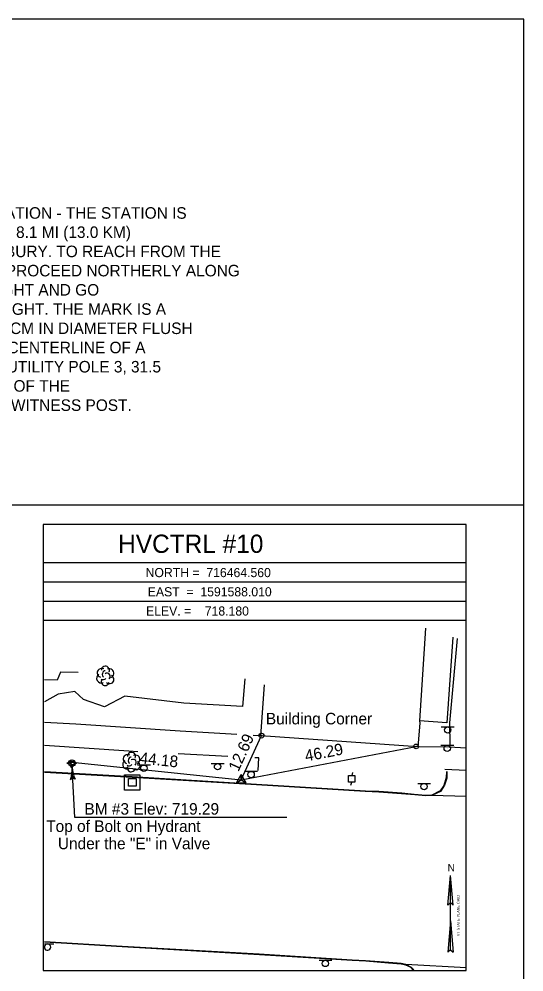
# Model space of a CAD drawing. Extents: x 1586965 to 1590952, y 716317 to 720029.
# Drawn here: x 1590820.9 to 1590952.2, y 716489.5 to 716737.4 of the extents above; entities that cross this region are included whole.
import ezdxf

# ---------------------------------------------------------------- set-up
doc = ezdxf.new("R2010")
doc.units = 0
for name, color, linetype in [('C_C', 7, 'Continuous'), ('CBP', 7, 'Continuous'), ('CPBM', 7, 'Continuous'), ('CPSM', 7, 'Continuous'), ('Default', 7, 'Continuous'), ('DS', 7, 'Continuous'), ('LAPB', 7, 'Continuous'), ('LBC', 7, 'Continuous'), ('LBF', 7, 'Continuous'), ('LTD', 7, 'Continuous'), ('NBL1', 7, 'Continuous'), ('NBL2', 7, 'Continuous'), ('NNA_P', 7, 'Continuous'), ('PET', 7, 'Continuous'), ('RC', 7, 'Continuous'), ('RDP', 7, 'Continuous'), ('RSW', 7, 'Continuous'), ('SSGN', 7, 'Continuous'), ('ULP', 7, 'Continuous'), ('UWFH', 7, 'Continuous')]:
    doc.layers.add(name, color=color, linetype=linetype)

msp = doc.modelspace()

# ---------------------------------------------------------------- linework, layer by layer
at = {"layer": 'CBP'}
for centre, radius in [((1590883.95, 716550.95), 0.625), ((1590883.95, 716550.95), 0.0833), ((1590924.14, 716548.14), 0.625), ((1590924.14, 716548.14), 0.0833), ((1590834.74, 716544), 0.625), ((1590834.74, 716544), 0.0833)]:
    msp.add_circle(centre, radius, dxfattribs=at)
at = {"layer": 'CPBM'}
for p, q in [((1590834.43, 716543.2), (1590834.43, 716544.2)), ((1590834.43, 716544.2), (1590835.43, 716544.2)), ((1590835.43, 716543.2), (1590834.43, 716543.2)), ((1590834.93, 716543.7), (1590834.93, 716543.7)), ((1590834.93, 716543.7), (1590834.93, 716543.7)), ((1590835.43, 716544.2), (1590835.43, 716543.2))]:
    msp.add_line(p, q, dxfattribs=at)
at = {"layer": 'CPSM'}
for p, q in [((1590877.42, 716538.69), (1590878.67, 716540.86)), ((1590879.92, 716538.69), (1590878.67, 716540.86)), ((1590878.67, 716539.42), (1590878.67, 716540.86)), ((1590877.42, 716538.69), (1590878.67, 716539.42)), ((1590877.42, 716538.69), (1590879.92, 716538.69)), ((1590878.67, 716539.42), (1590878.67, 716539.42)), ((1590878.67, 716539.42), (1590879.92, 716538.69))]:
    msp.add_line(p, q, dxfattribs=at)
at = {"layer": 'Default'}
for p, q in [((1590878.67, 716539.42), (1590883.95, 716550.95)), ((1590878.67, 716539.42), (1590924.14, 716548.14)), ((1590834.74, 716544), (1590878.67, 716539.42)), ((1590834.54, 716539.88), (1590834.72, 716540.37)), ((1590835.42, 716529.68), (1590834.71, 716542.7)), ((1590835.19, 716539.92), (1590834.96, 716540.39)), ((1590834.3, 716539.57), (1590834.87, 716539.85)), ((1590835.46, 716539.64), (1590834.87, 716539.85)), ((1590890.57, 716529.68), (1590835.42, 716529.68))]:
    msp.add_line(p, q, dxfattribs=at)
for centre, start, end in [((1590826.16, 716542.23), 341.9202, 3.1073), ((1590843.27, 716543.16), 183.1148, 204.3019)]:
    msp.add_arc(centre, 8.57, start, end, dxfattribs=at)
at = {"layer": 'DS'}
for p, q in [((1590848.34, 716540.77), (1590852.34, 716540.77)), ((1590848.34, 716536.77), (1590848.34, 716540.77)), ((1590852.34, 716540.77), (1590852.34, 716536.77)), ((1590849.34, 716537.77), (1590849.34, 716539.77)), ((1590849.34, 716539.77), (1590851.34, 716539.77)), ((1590851.34, 716537.77), (1590849.34, 716537.77)), ((1590850.35, 716538.77), (1590850.35, 716538.77)), ((1590850.35, 716538.77), (1590850.35, 716538.77)), ((1590851.34, 716539.77), (1590851.34, 716537.77)), ((1590852.34, 716536.77), (1590848.34, 716536.77))]:
    msp.add_line(p, q, dxfattribs=at)
at = {"layer": 'LAPB'}
msp.add_lwpolyline([(1590879.6, 716565.72), (1590879.04, 716558.49), (1590863.72, 716559.41), (1590848.43, 716561.17), (1590843.12, 716558.45), (1590837.66, 716560.37), (1590835.41, 716562.4), (1590831.03, 716561.73), (1590827.48, 716559.78)], dxfattribs=at)
at = {"layer": 'LBC'}
for points in [[(1590926.63, 716578.87), (1590925.04, 716554.77), (1590925.13, 716554.17), (1590924.63, 716547.99), (1590883.81, 716550.89), (1590884.72, 716564.13)], [(1590836.24, 716567.34), (1590831.64, 716567.44), (1590830.83, 716565.35), (1590827.48, 716565.47)]]:
    msp.add_lwpolyline(points, dxfattribs=at)
at = {"layer": 'LBF'}
msp.add_lwpolyline([(1590933.71, 716576.58), (1590932.16, 716554.31), (1590925.04, 716554.77)], dxfattribs=at)
at = {"layer": 'LTD'}
for p, q in [((1590843.29, 716566.54), (1590843.29, 716566.54)), ((1590843.29, 716566.54), (1590843.29, 716566.54)), ((1590850.07, 716544.12), (1590850.07, 716544.12)), ((1590850.07, 716544.12), (1590850.07, 716544.12))]:
    msp.add_line(p, q, dxfattribs=at)
for centre in [(1590843.34, 716567.97), (1590850.12, 716545.55)]:
    msp.add_arc(centre, 1.05, 335.5272, 180.9563, dxfattribs=at)
for centre, major_axis, ratio, start_param, end_param in [((1590842.5, 716567.2), (1.21, -0.51), 0.895232, 1.570796, 4.712389), ((1590843.08, 716566.99), (-0.208, -0.792), 0.645439, 3.141593, 6.283185), ((1590844.33, 716567.12), (-1.14, -0.48), 0.949671, 1.570796, 4.712389), ((1590842.21, 716565.83), (0.58, -1.04), 0.959034, 3.141593, 6.283185), ((1590843.29, 716565.04), (0.26, 1.06), 0.942809, 1.570796, 4.712389), ((1590842.83, 716565.78), (-0.625, -0.083), 0.423636, 0, 3.141593), ((1590843.79, 716566.37), (-0.5, 0.667), 0.989748, 3.141593, 6.283185), ((1590844.29, 716565.7), (-1.09, 0.79), 0.841452, 1.570796, 4.712389), ((1590849.28, 716544.79), (1.21, -0.51), 0.895232, 1.570796, 4.712389), ((1590849.86, 716544.58), (-0.208, -0.792), 0.645439, 3.141593, 6.283185), ((1590851.11, 716544.7), (-1.14, -0.48), 0.949671, 1.570796, 4.712389), ((1590848.99, 716543.41), (0.58, -1.04), 0.959034, 3.141593, 6.283185), ((1590850.07, 716542.62), (0.26, 1.06), 0.942809, 1.570796, 4.712389), ((1590849.61, 716543.37), (-0.625, -0.083), 0.423636, 0, 3.141593), ((1590850.57, 716543.95), (-0.5, 0.667), 0.989748, 3.141593, 6.283185), ((1590851.07, 716543.29), (-1.09, 0.79), 0.841452, 1.570796, 4.712389)]:
    msp.add_ellipse(centre, major_axis=major_axis, ratio=ratio, start_param=start_param, end_param=end_param, dxfattribs=at)
at = {"layer": 'NBL1'}
msp.add_lwpolyline([(1590312.19, 716317.36), (1590952.19, 716317.36), (1590952.19, 716737.36), (1590312.19, 716737.36)], close=True, dxfattribs=at)
at = {"layer": 'NBL2'}
for p, q in [((1590312.19, 716611.03), (1590952.19, 716611.03)), ((1590937.19, 716595.86), (1590827.19, 716595.86)), ((1590937.19, 716590.86), (1590827.19, 716590.86)), ((1590937.19, 716585.86), (1590827.19, 716585.86)), ((1590937.19, 716580.86), (1590827.19, 716580.86))]:
    msp.add_line(p, q, dxfattribs=at)
msp.add_lwpolyline([(1590827.19, 716489.86), (1590937.19, 716489.86), (1590937.19, 716605.86), (1590827.19, 716605.86)], close=True, dxfattribs=at)
at = {"layer": 'NNA_P'}
for p, q in [((1590932.4, 716506.8), (1590933.1, 716514.59)), ((1590933.1, 716495.21), (1590933.1, 716514.59)), ((1590933.79, 716506.8), (1590933.1, 716514.59)), ((1590932.4, 716506.8), (1590933.1, 716507.56)), ((1590933.79, 716506.8), (1590933.1, 716507.56)), ((1590933.1, 716502.74), (1590932.38, 716494.57)), ((1590933.1, 716502.74), (1590933.82, 716494.57)), ((1590933.1, 716495.21), (1590932.38, 716494.57)), ((1590933.1, 716495.21), (1590933.82, 716494.57))]:
    msp.add_line(p, q, dxfattribs=at)
at = {"layer": 'PET'}
for points in [[(1590937.2, 716535.07), (1590928.26, 716535.38), (1590926.67, 716535.25), (1590923.84, 716535.53), (1590920.38, 716535.82), (1590914.44, 716536.24), (1590910.94, 716536.39), (1590882.62, 716538.14), (1590850.34, 716540.02), (1590827.48, 716541.39)], [(1590937.2, 716490.53), (1590921.5, 716491.4), (1590920.28, 716491.67), (1590917.05, 716491.9), (1590910.99, 716492.33), (1590907.52, 716492.55), (1590883.32, 716494.1), (1590847.75, 716496.09), (1590827.48, 716497.31)]]:
    msp.add_lwpolyline(points, dxfattribs=at)
at = {"layer": 'RC'}
for points in [[(1590932.03, 716541.63), (1590932.01, 716540.03), (1590931.34, 716537.93), (1590930.41, 716536.59), (1590928.2, 716535.44), (1590926.68, 716535.34), (1590923.64, 716535.67), (1590920.4, 716535.98), (1590914.49, 716536.42), (1590910.96, 716536.53), (1590882.68, 716538.26), (1590850.29, 716540.2), (1590827.48, 716541.53)], [(1590923.41, 716490.01), (1590922.86, 716490.58), (1590921.51, 716491.25), (1590920.27, 716491.52), (1590916.96, 716491.74), (1590911.04, 716492.25), (1590907.51, 716492.47), (1590883.41, 716493.92), (1590847.73, 716495.96), (1590827.48, 716497.21)]]:
    msp.add_lwpolyline(points, dxfattribs=at)
at = {"layer": 'RDP'}
for points in [[(1590934.81, 716576.25), (1590932.87, 716554.26), (1590932.92, 716548.45)], [(1590932.11, 716541.64), (1590932.13, 716539.92), (1590931.56, 716538.06), (1590930.51, 716536.39), (1590928.26, 716535.38)], [(1590923.53, 716490.01), (1590922.96, 716490.6), (1590921.5, 716491.4)]]:
    msp.add_lwpolyline(points, dxfattribs=at)
at = {"layer": 'RSW'}
for points in [[(1590877.5, 716551.26), (1590862.82, 716552.14), (1590835.64, 716553.89), (1590827.48, 716554.37)], [(1590883.81, 716550.89), (1590881.78, 716551.01)], [(1590851.78, 716546.77), (1590849.42, 716546.89), (1590827.48, 716548.35)], [(1590937.2, 716547.68), (1590932.74, 716547.92), (1590924.63, 716547.99)], [(1590875.19, 716545.55), (1590862.31, 716546.22)], [(1590883.08, 716541.9), (1590883.26, 716545.13), (1590882.21, 716545.19)], [(1590937.2, 716541.89), (1590931.58, 716542.17)]]:
    msp.add_lwpolyline(points, dxfattribs=at)
at = {"layer": 'SSGN'}
for p, q in [((1590930.71, 716553.25), (1590934.05, 716553.25)), ((1590932.36, 716552.42), (1590932.36, 716552.42)), ((1590930.6, 716548.49), (1590933.94, 716548.49)), ((1590932.25, 716547.66), (1590932.25, 716547.66)), ((1590851.72, 716543.31), (1590855.05, 716543.31)), ((1590870.88, 716543.71), (1590874.22, 716543.71)), ((1590872.53, 716542.88), (1590872.53, 716542.88)), ((1590853.36, 716542.47), (1590853.36, 716542.47)), ((1590879.59, 716541.66), (1590882.92, 716541.66)), ((1590881.24, 716540.82), (1590881.24, 716540.82)), ((1590924.56, 716538.53), (1590927.9, 716538.53)), ((1590926.21, 716537.7), (1590926.21, 716537.7)), ((1590827.48, 716496.75), (1590829.98, 716496.75)), ((1590827.48, 716496.11), (1590827.48, 716495.73)), ((1590828.29, 716495.92), (1590828.29, 716495.92)), ((1590898.9, 716492.51), (1590902.23, 716492.51)), ((1590900.54, 716491.68), (1590900.54, 716491.68))]:
    msp.add_line(p, q, dxfattribs=at)
for centre in [(1590932.36, 716552.42), (1590932.25, 716547.66), (1590853.36, 716542.47), (1590872.53, 716542.88), (1590881.24, 716540.82), (1590926.21, 716537.7), (1590900.54, 716491.68)]:
    msp.add_circle(centre, 0.833, dxfattribs=at)
msp.add_arc((1590828.29, 716495.92), 0.833, 193.1074, 166.8926, dxfattribs=at)
at = {"layer": 'ULP'}
for p, q in [((1590906.59, 716538.88), (1590906.59, 716540.54)), ((1590906.59, 716540.54), (1590908.26, 716540.54)), ((1590907.59, 716541.38), (1590907.42, 716540.54)), ((1590908.26, 716540.54), (1590908.26, 716538.88)), ((1590908.26, 716538.88), (1590906.59, 716538.88)), ((1590907.17, 716538.04), (1590907.42, 716538.88)), ((1590907.42, 716539.71), (1590907.42, 716539.71))]:
    msp.add_line(p, q, dxfattribs=at)
at = {"layer": 'UWFH'}
msp.add_line((1590834.6, 716543.81), (1590834.6, 716543.81), dxfattribs=at)
for centre, radius in [((1590833.6, 716543.81), 0.167), ((1590834.6, 716543.81), 0.833), ((1590834.6, 716542.81), 0.167), ((1590835.6, 716543.81), 0.167)]:
    msp.add_circle(centre, radius, dxfattribs=at)

# ---------------------------------------------------------------- texts
at = {"layer": 'C_C'}
for s, p in [('Building Corner', (1590885.08, 716553.87)), ('BM #3 Elev: 719.29', (1590837.9, 716530.39)), ('Top of Bolt on Hydrant', (1590827.95, 716525.89)), ('Under the "E" in Valve', (1590830.99, 716521.39))]:
    msp.add_text(s, height=3, dxfattribs=at).set_placement(p)
at = {"layer": 'Default'}
for s, p in [('DESCRIBED BY VERMONT AGENCY OF TRANSPORTATION 1996 (DJM) GENERAL LOCATION - THE STATION IS ', (1590651.61, 716685.42)), ('LOCATED IN THE TOWN OF STOWE, 1.2 MI (1.9 KM) NORTHWEST OF STOWE VILLAGE, 8.1 MI (13.0 KM) ', (1590651.61, 716680.42)), ('SOUTHWEST OF MORRISVILLE, AND 9.8 MI (15.8 KM) NORTH NORTHEAST OF WATERBURY. TO REACH FROM THE ', (1590651.61, 716675.42)), ('JUNCTION OF VERMONT ROUTE 100 AND VERMONT ROUTE 108 IN STOWE VILLAGE, PROCEED NORTHERLY ALONG ', (1590651.61, 716670.42)), ('ROUTE 108 FOR 1.7 MI (2.7 KM) TO CAPE COD ROAD (TH 31) ON THE RIGHT. TURN RIGHT AND GO ', (1590651.61, 716665.42)), ('NORTHEAST ALONG CAPE COD ROAD FOR 0.15 MI (0.24 KM) TO THE MARK ON THE RIGHT. THE MARK IS A ', (1590651.61, 716660.42)), ('STATE OF VERMONT SURVEY DISK SET IN THE TOP OF A CONCRETE MONUMENT 30 CM IN DIAMETER FLUSH ', (1590651.61, 716655.42)), ('WITH THE GROUND SURFACE. IT IS LOCATED 176.5 FT (53.8 M) SOUTHWEST OF THE CENTERLINE OF A ', (1590651.61, 716650.42)), ('PAVED DRIVE TO VILLAGE GREEN CONDOMINIUMS, 66.5 FT (20.3 M) NORTHEAST OF UTILITY POLE 3, 31.5 ', (1590651.61, 716645.42)), ('FT (9.6 M) NORTH OF A HIGHWAY SIGN (SPEED LIMIT 35) , 14.5 FT (4.4 M) SOUTHEAST OF THE ', (1590651.61, 716640.42)), ('CENTERLINE OF CAPE COD ROAD (TH 31) , AND 1 FT (0.3 M) WEST OF A FIBERGLASS WITNESS POST. ', (1590651.61, 716635.42))]:
    msp.add_text(s, height=3, dxfattribs=at).set_placement(p)
for s, rotation, p in [('12.69', 65.4424, (1590877.93, 716541.39)), ('46.29', 10.8679, (1590895.52, 716544.18)), ('44.18', 354.0371, (1590852.12, 716543.7))]:
    msp.add_text(s, height=3, rotation=rotation, dxfattribs=at).set_placement(p)
at = {"layer": 'NBL2'}
for s, height, p in [('     HVCTRL #10    ', 4.75, (1590837.84, 716598.49)), ('NORTH =  716464.560 ', 2.375, (1590853.81, 716592.18)), ('EAST  =  1591588.010', 2.375, (1590854.37, 716587.18)), ('ELEV. =    718.180  ', 2.375, (1590853.92, 716582.18))]:
    msp.add_text(s, height=height, dxfattribs=at).set_placement(p)
at = {"layer": 'NNA_P'}
msp.add_text('N', height=1.97, dxfattribs=at).set_placement((1590932.33, 716515.6))
msp.add_text('VT STATE PLANE GRID', height=0.7, rotation=90.0204, dxfattribs=at).set_placement((1590935.45, 716498.78))

doc.saveas('drawing.dxf')
